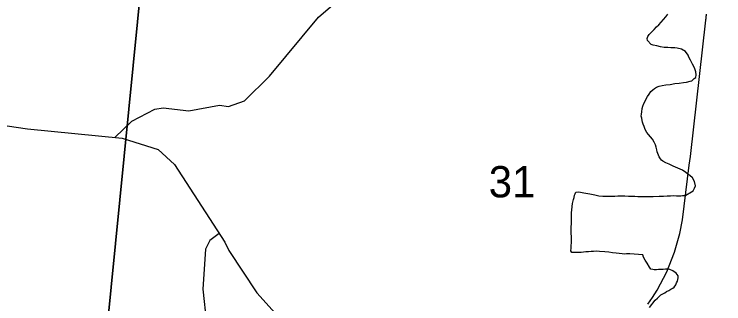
# Model space of a CAD drawing. Extents: x -1.4 to 35.4, y 0 to 22.
# Drawn here: x 26.446 to 27.393, y 16.027 to 16.414 of the extents above; entities that cross this region are included whole.
import ezdxf

# ---------------------------------------------------------------- set-up
doc = ezdxf.new("R2010")
doc.units = 0
for name, color, linetype in [('GM_X_County_Text', 7, 'Continuous'), ('GM_X_Minor_River', 7, 'Continuous'), ('GM_X_Section', 7, 'Continuous'), ('GM_X_Section_Text', 7, 'Continuous')]:
    doc.layers.add(name, color=color, linetype=linetype)

msp = doc.modelspace()

# ---------------------------------------------------------------- linework, layer by layer
at = {"layer": 'GM_X_County_Text'}
msp.add_lwpolyline([(27.29188, 16.02648), (27.29829, 16.03567), (27.30429, 16.04513), (27.31737, 16.06989), (27.32776, 16.09589), (27.33468, 16.12092), (27.33817, 16.13942), (27.34735, 16.21241), (27.34877, 16.22368), (27.36952, 16.40609), (27.36953, 16.40619), (27.36953, 16.40623), (27.36954, 16.40633), (27.36955, 16.4064), (27.36955, 16.40642), (27.36956, 16.4065), (27.36957, 16.40652), (27.36958, 16.4066), (27.36959, 16.4067), (27.3696, 16.4068), (27.3696, 16.40681), (27.36961, 16.40689), (27.36961, 16.40691), (27.36962, 16.40699), (27.36962, 16.40702), (27.36963, 16.40708), (27.36963, 16.40712), (27.36964, 16.40717), (27.36964, 16.40722), (27.36965, 16.40727), (27.36965, 16.40732), (27.36966, 16.40736), (27.36967, 16.40743), (27.36967, 16.40746), (27.36968, 16.40755), (27.36969, 16.40764), (27.3697, 16.40774), (27.36971, 16.40783), (27.36972, 16.40793), (27.36973, 16.40802), (27.36974, 16.40812), (27.36975, 16.40821), (27.36976, 16.4083), (27.36977, 16.4084), (27.36978, 16.40849), (27.36979, 16.40859), (27.3698, 16.40868), (27.36981, 16.40877), (27.36982, 16.40887), (27.36983, 16.40896), (27.36984, 16.40906), (27.36985, 16.40915), (27.36987, 16.40934), (27.36988, 16.40943), (27.36989, 16.40953), (27.3699, 16.40962), (27.36991, 16.40972), (27.36992, 16.40981), (27.36994, 16.41), (27.36994, 16.41009), (27.36995, 16.41019), (27.36996, 16.41028), (27.36997, 16.41038), (27.36999, 16.41056), (27.37, 16.41066), (27.37001, 16.41075), (27.37002, 16.41085), (27.37003, 16.41094), (27.37004, 16.41104), (27.37005, 16.41113), (27.37006, 16.41122), (27.37008, 16.41141), (27.37009, 16.41151), (27.3701, 16.4116), (27.3701, 16.4117), (27.37011, 16.41179), (27.37012, 16.41188), (27.37013, 16.41198), (27.37014, 16.41207), (27.37015, 16.41217), (27.37016, 16.41226), (27.37017, 16.41236), (27.37018, 16.41245), (27.37019, 16.41254), (27.3702, 16.41273), (27.37021, 16.41283), (27.37022, 16.41292), (27.37023, 16.41302), (27.37024, 16.41311), (27.37025, 16.4132), (27.37026, 16.4133), (27.37027, 16.41339), (27.37028, 16.41349), (27.37028, 16.41358), (27.37029, 16.41368), (27.3703, 16.41377), (27.37031, 16.41386), (27.37032, 16.41396), (27.37033, 16.41405)], dxfattribs=at)
at = {"layer": 'GM_X_Minor_River'}
for points in [[(26.58062, 16.24919), (26.60311, 16.27109), (26.63416, 16.28717), (26.6452, 16.28884), (26.67926, 16.28472), (26.72038, 16.29224), (26.73249, 16.29085), (26.75387, 16.29801), (26.78716, 16.33113), (26.85248, 16.40995), (26.88414, 16.43741)], [(27.29602, 16.31077), (27.29871, 16.313), (27.30102, 16.31486), (27.3037, 16.31634), (27.30714, 16.3178), (27.31094, 16.3185), (27.3159, 16.31956), (27.32198, 16.32022), (27.32807, 16.32126), (27.33378, 16.32192), (27.33948, 16.32259), (27.34367, 16.32328), (27.34862, 16.32434), (27.35091, 16.32506), (27.35399, 16.32805), (27.35591, 16.32954), (27.35673, 16.33295), (27.35604, 16.33714), (27.35422, 16.34211), (27.35164, 16.3471), (27.34907, 16.35246), (27.34686, 16.35668), (27.34576, 16.35936), (27.34242, 16.36435), (27.33715, 16.3671), (27.3311, 16.36872), (27.32807, 16.36915), (27.3258, 16.36919), (27.32276, 16.36923), (27.31858, 16.36931), (27.31403, 16.36938), (27.30911, 16.37022), (27.3042, 16.37182), (27.29928, 16.37266), (27.29626, 16.37347), (27.29179, 16.37887), (27.29107, 16.38154), (27.29187, 16.38419), (27.29381, 16.38682), (27.29729, 16.39056), (27.30037, 16.39355), (27.30346, 16.39692), (27.30655, 16.39991), (27.30964, 16.40328), (27.31273, 16.40703), (27.3162, 16.41039), (27.31892, 16.41415)], [(27.19389, 16.09545), (27.19047, 16.0955), (27.18937, 16.0978), (27.18981, 16.10159), (27.18987, 16.10501), (27.18992, 16.10843), (27.18997, 16.11147), (27.19001, 16.11413), (27.19006, 16.11717), (27.18974, 16.12097), (27.1898, 16.12477), (27.18988, 16.13009), (27.18994, 16.13389), (27.19001, 16.13769), (27.19007, 16.14187), (27.19013, 16.14567), (27.19018, 16.14871), (27.19062, 16.1525), (27.19151, 16.16085), (27.19192, 16.16274), (27.19274, 16.16653), (27.19354, 16.16917), (27.19435, 16.1722), (27.19514, 16.17409), (27.19593, 16.17598), (27.20012, 16.17667), (27.20655, 16.17542), (27.2145, 16.17377), (27.22131, 16.17252), (27.2266, 16.17129), (27.23191, 16.17082), (27.2376, 16.17073), (27.24216, 16.17103), (27.24786, 16.17094), (27.25204, 16.17125), (27.25659, 16.17118), (27.26153, 16.17109), (27.26608, 16.17102), (27.27063, 16.17094), (27.27481, 16.17088), (27.2786, 16.17043), (27.28315, 16.17036), (27.28771, 16.17028), (27.2934, 16.17057), (27.2991, 16.17048), (27.30708, 16.17072), (27.31277, 16.17101), (27.31771, 16.17131), (27.32227, 16.17123), (27.32645, 16.17154), (27.33024, 16.17148), (27.33328, 16.17143), (27.33594, 16.17139), (27.33822, 16.17173), (27.34088, 16.17169), (27.34278, 16.17204), (27.35044, 16.17647), (27.35236, 16.17796), (27.35432, 16.18135), (27.35551, 16.18475), (27.35446, 16.19046), (27.3515, 16.19545), (27.34814, 16.19855), (27.3455, 16.20011), (27.34288, 16.20244), (27.33838, 16.20555), (27.33197, 16.20832), (27.32594, 16.21108), (27.32066, 16.21344), (27.31614, 16.21542), (27.312, 16.21777), (27.31012, 16.21894), (27.30901, 16.22086), (27.30715, 16.22355), (27.30605, 16.22547), (27.30532, 16.22776), (27.3046, 16.23005), (27.30388, 16.23272), (27.30318, 16.23615), (27.3021, 16.23959), (27.30063, 16.24304), (27.29804, 16.24688), (27.29543, 16.25034), (27.29283, 16.25343), (27.29059, 16.25613), (27.28912, 16.25881), (27.28801, 16.26111), (27.28692, 16.26379), (27.28583, 16.26685), (27.28511, 16.26952), (27.28439, 16.27181), (27.28406, 16.27486), (27.28334, 16.27791), (27.28338, 16.28019), (27.28382, 16.2836), (27.28464, 16.28777), (27.28546, 16.29118), (27.28665, 16.29458), (27.29173, 16.30399), (27.29368, 16.307), (27.29602, 16.31077)], [(26.3975, 16.27075), (26.46407, 16.26103), (26.59051, 16.24818), (26.63839, 16.23314), (26.66037, 16.21332), (26.72733, 16.10939), (26.73279, 16.09827), (26.77035, 16.04166), (26.8312, 15.97395), (26.84425, 15.96267), (26.86758, 15.95345), (26.92606, 15.93744)], [(26.71987, 16.12096), (26.70726, 16.1117), (26.70172, 16.10004), (26.69799, 16.04657), (26.70315, 16.00127)], [(27.29408, 16.02197), (27.30183, 16.03172), (27.30491, 16.03471), (27.30722, 16.03695), (27.30954, 16.0392), (27.31221, 16.04029), (27.31451, 16.04177), (27.31681, 16.04326), (27.31987, 16.04473), (27.32256, 16.04658), (27.32524, 16.04806), (27.32716, 16.04917), (27.32948, 16.05217), (27.33029, 16.05519), (27.33184, 16.05745), (27.33226, 16.05934), (27.33267, 16.06162), (27.33271, 16.06427), (27.32974, 16.06813), (27.32561, 16.07123), (27.32146, 16.07282), (27.31843, 16.07325), (27.31577, 16.07329), (27.31235, 16.07297), (27.30856, 16.07303), (27.30627, 16.07269), (27.30361, 16.07235), (27.30058, 16.0724), (27.29868, 16.07282), (27.29603, 16.07324), (27.29418, 16.07593), (27.29123, 16.0813), (27.28826, 16.08553), (27.28642, 16.08936), (27.28533, 16.09242), (27.26789, 16.09384), (27.26372, 16.09391), (27.26105, 16.09358), (27.25764, 16.09402), (27.25385, 16.09446), (27.24968, 16.09452), (27.24475, 16.09499), (27.23983, 16.09583), (27.23452, 16.09629), (27.2277, 16.09679), (27.22315, 16.09724), (27.21935, 16.09693), (27.21631, 16.09698), (27.21289, 16.09665), (27.20947, 16.09633), (27.20605, 16.096), (27.203, 16.09567), (27.19959, 16.09573), (27.19654, 16.0954), (27.19389, 16.09545)]]:
    msp.add_lwpolyline(points, dxfattribs=at)
at = {"layer": 'GM_X_Section'}
for points in [[(26.64566, 16.75445), (26.54696, 15.75756), (25.5939, 15.85057), (25.57689, 15.85237), (25.66845, 16.85281)], [(27.67732, 16.65174), (27.5793, 15.64992), (26.56663, 15.75608), (26.54696, 15.75756), (26.64566, 16.75445)]]:
    msp.add_lwpolyline(points, close=True, dxfattribs=at)

# ---------------------------------------------------------------- texts
at = {"layer": 'GM_X_Section_Text'}
msp.add_text('31', height=0.041856, rotation=0.00001, dxfattribs=at).set_placement((27.07964, 16.16922))

doc.saveas('drawing.dxf')
